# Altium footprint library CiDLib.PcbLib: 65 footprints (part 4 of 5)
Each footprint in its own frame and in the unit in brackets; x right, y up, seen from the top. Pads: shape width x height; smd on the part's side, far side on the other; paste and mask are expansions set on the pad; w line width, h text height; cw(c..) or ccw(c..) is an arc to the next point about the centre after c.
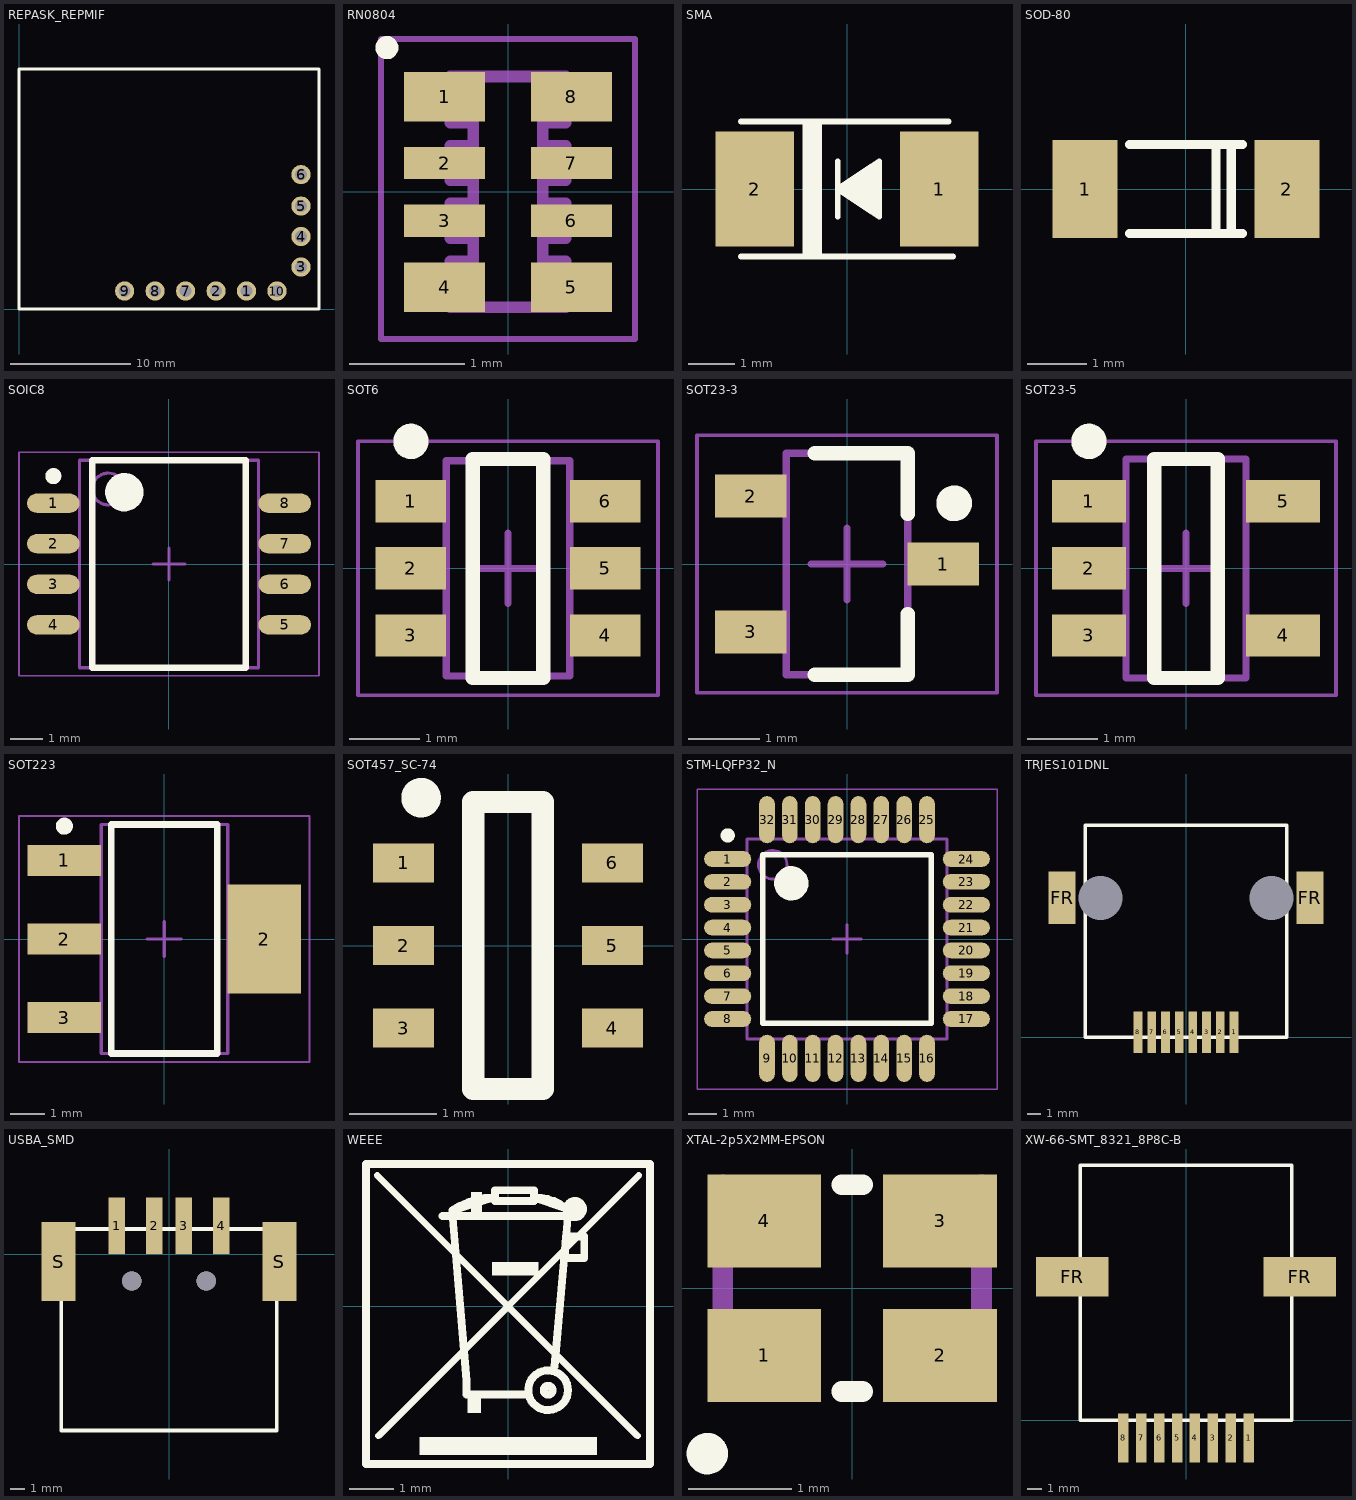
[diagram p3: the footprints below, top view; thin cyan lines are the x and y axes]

## REPASK_REPMIF [mm]
pads (10):
  round 1.6 hole 1: 1(18.96,1.5) 2(16.42,1.5) 3(23.5,3.5) 4(23.5,6.04) 5(23.5,8.58) 6(23.5,11.2) 7(13.88,1.5) 8(11.34,1.5) 9(8.8,1.5) 10(21.5,1.5)
Top Overlay:
  lines w0.254: 0,0 0,20 25,20 25,0 0,0
3D body: height 10, standoff 0, extent 0.001,0.001 24.999,19.999

## RN0804 [mm] "Chip Array, ConvexS, 8-Leads, Pitch 0,50mm,  Body 2,00x1,00mm,  IPC Medium Density"
height 0.6
pads (8):
  rect 0.7x0.43 smd: 1(-0.55,0.825) 4(-0.55,-0.825) 5(0.55,-0.825) 8(0.55,0.825)
  rect 0.7x0.28 smd: 2(-0.55,0.25) 3(-0.55,-0.25) 6(0.55,-0.25) 7(0.55,0.25)
Top Overlay:
  circle w0.1: c-1.05,1.25 r0.05
Top Solder:
  region: 0.2,-0.56 0.2,-1.09 0.8,-1.09 0.8,-0.56
  region: 0.2,1.09 0.2,0.56 0.8,0.56 0.8,1.09
  region: -0.8,-0.56 -0.8,-1.09 -0.2,-1.09 -0.2,-0.56
  region: -0.8,-0.06 -0.8,-0.44 -0.2,-0.44 -0.2,-0.06
  region: 0.2,-0.06 0.2,-0.44 0.8,-0.44 0.8,-0.06
  region: -0.8,1.09 -0.8,0.56 -0.2,0.56 -0.2,1.09
  region: 0.2,0.44 0.2,0.06 0.8,0.06 0.8,0.44
  region: -0.8,0.44 -0.8,0.06 -0.2,0.06 -0.2,0.44
Mechanical 15:
  lines w0.05: -1.1,-1.275 1.1,-1.275 1.1,1.325 -1.1,1.325 -1.1,-1.275
Mechanical 16:
  lines w0.1: -0.5,-1 -0.5,-0.6 -0.3,-0.6 -0.3,-0.4 -0.5,-0.4 -0.5,-0.1 -0.3,-0.1 -0.3,0.1 -0.5,0.1 -0.5,0.4 -0.3,0.4 -0.3,0.6 -0.5,0.6 -0.5,1 0.5,1 0.5,0.6 0.3,0.6 0.3,0.4 0.5,0.4 0.5,0.1 0.3,0.1 0.3,-0.1 0.5,-0.1 0.5,-0.4 0.3,-0.4 0.3,-0.6 0.5,-0.6 0.5,-1 -0.5,-1

## SMA [mm]
pads (2):
  rect 1.7x2.5 smd: 1(2,0) 2(-2,0)
Top Overlay:
  lines w0.127: -2.3,-1.46 2.3,-1.46 ; -2.3,1.46 2.2,1.46 ; -0.9,-1.4 -0.9,1.4 ; -0.8,-1.4 -0.8,1.4 ; -0.7,-1.4 -0.7,1.4 ; -0.6,-1.4 -0.6,1.4 ; -0.2,-0.6 -0.2,0 ; -0.2,0.6 -0.2,0 ; -0.1,0 0,0 ; 0,-0.1 0,0 ; 0,0.1 0,0 ; 0.1,-0.1 0.1,0.1 ; 0.2,-0.2 0.2,0.2 ; 0.3,-0.3 0.3,0.3 ; 0.5,-0.4 0.5,0.4 ; 0.6,-0.5 0.6,0.5 ; -0.2,0 0.4,-0.4 ; -0.2,0 0.4,0.4 ; 0.4,-0.4 0.7,-0.6 0.7,0.6 0.4,0.4 ; 0.4,-0.4 0.4,0.4
3D body "User Library-DO-214AC_SMA.step": height 2.15, standoff -0.05, extent -2.5,-1.35 2.5,1.35

## SOD-80 [mm]
height 1.5
pads (2):
  rect 1.1x1.65 smd mask+0.064: 1(-1.7,0) 2(1.7,0)
Top Overlay:
  lines w0.152: -0.953,-0.75 0.953,-0.75 ; -0.953,0.75 0.953,0.75 ; 0.508,-0.75 0.508,0.75 ; 0.762,-0.75 0.762,0.75

## SOIC8 [mm] "SOIC, 8-Leads, Body 6,20x5,30mm, Pitch 1,27mm, IPC Medium Density"
height 2
pads (8):
  oval 1.65x0.6 smd: 1(-3.625,1.905) 2(-3.625,0.635) 3(-3.625,-0.635) 4(-3.625,-1.905) 5(3.625,-1.905) 6(3.625,-0.635) 7(3.625,0.635) 8(3.625,1.905)
Top Overlay:
  circle w0.25: c-3.625,2.755 r0.125
  circle w0.6: c-1.4,2.25 r0.3
  lines w0.2: -2.4,-3.25 -2.4,3.25 2.4,3.25 2.4,-3.25 -2.4,-3.25
Mechanical 13:
  circle w0.1: c-1.9,2.35 r0.5
  lines w0.1: -2.8,-3.25 -2.8,3.25 2.8,3.25 2.8,-3.25 -2.8,-3.25
Mechanical 15:
  lines w0.05: -4.7,-3.5 -4.7,3.5 4.7,3.5 4.7,-3.5 -4.7,-3.5
  lines w0.1: -0.5,0 0.5,0 ; 0,-0.5 0,0.5
3D body: height 2, standoff 0.1, extent -2.8,-3.25 2.8,3.25

## SOT6 [mm] "SOT23, 6-Leads, Body 2,90x2,80mm, Pitch 0,95mm, IPC Medium Density"
height 1.1
pads (6):
  rect 1x0.6 smd: 1(-1.375,0.95) 2(-1.375,0) 3(-1.375,-0.95) 4(1.375,-0.95) 5(1.375,0) 6(1.375,0.95)
Top Overlay:
  circle w0.25: c-1.375,1.8 r0.125
  lines w0.2: -0.5,-1.55 0.5,-1.55 0.5,1.55 -0.5,1.55 -0.5,-1.55
Mechanical 13:
  lines w0.1: -0.875,-1.525 -0.875,1.525 0.875,1.525 0.875,-1.525 -0.875,-1.525
Mechanical 15:
  lines w0.05: -2.125,-1.8 -2.125,1.8 2.125,1.8 2.125,-1.8 -2.125,-1.8
  lines w0.1: -0.5,0 0.5,0 ; 0,-0.5 0,0.5
3D body: height 1.1, standoff 0.1, extent -0.875,-1.525 0.875,1.525

## SOT23-3 [mm]
height 1.2
pads (3):
  rect 1x0.6 smd: 1(1.35,0) 2(-1.35,0.95) 3(-1.35,-0.95)
Top Overlay:
  circle w0.25: c1.5,0.85 r0.125
  lines w0.2: -0.45,-1.55 0.85,-1.55 0.85,-0.7 ; -0.45,1.55 0.85,1.55 0.85,0.7
Mechanical 13:
  lines w0.1: -0.85,-1.55 -0.85,1.55 0.85,1.55 0.85,-1.55 -0.85,-1.55
Mechanical 15:
  lines w0.05: -2.1,-1.8 -2.1,1.8 2.1,1.8 2.1,-1.8 -2.1,-1.8
  lines w0.1: -0.5,0 0.5,0 ; 0,-0.5 0,0.5
3D body "CircuitWorks-SOT-23.step": height 1.1, standoff 0, extent -1.25,-1.5 1.25,1.5

## SOT23-5 [mm]
height 1.2
pads (5):
  rect 1.05x0.6 smd: 1(-1.375,0.95) 2(-1.375,0) 3(-1.375,-0.95) 4(1.375,-0.95) 5(1.375,0.95)
Top Overlay:
  circle w0.25: c-1.375,1.8 r0.125
  lines w0.2: -0.45,-1.55 -0.45,1.55 0.45,1.55 0.45,-1.55 -0.45,-1.55
Mechanical 13:
  lines w0.1: -0.85,-1.55 0.85,-1.55 0.85,1.55 -0.85,1.55 -0.85,-1.55
Mechanical 15:
  lines w0.05: -2.125,-1.8 2.125,-1.8 2.125,1.8 -2.125,1.8 -2.125,-1.8
  lines w0.1: -0.5,0 0.5,0 ; 0,-0.5 0,0.5
3D body: height 1.2, standoff 0.1, extent -0.85,-1.55 0.85,1.55

## SOT223 [mm] "SOT223, 4-Leads, Body 6,50x7,00mm (avg), Pitch 2,30mm, IPC Medium Density"
height 1.7
pads (4):
  rect 2.15x0.9 smd: 1(-2.925,2.3) 2(-2.925,0) 3(-2.925,-2.3)
  rect 2.15x3.2 smd: 2(2.925,0)
Top Overlay:
  circle w0.25: c-2.925,3.3 r0.125
  lines w0.2: -1.55,-3.35 1.55,-3.35 1.55,3.35 -1.55,3.35 -1.55,-3.35
Mechanical 13:
  lines w0.1: -1.85,-3.35 1.85,-3.35 1.85,3.35 -1.85,3.35 -1.85,-3.35
Mechanical 15:
  lines w0.05: -4.25,-3.6 4.25,-3.6 4.25,3.6 -4.25,3.6 -4.25,-3.6
  lines w0.1: -0.5,0 0.5,0 ; 0,-0.5 0,0.5
3D body "User Library-SOT-223-1.step": height 1.65, standoff 0, extent -3.5,-3.25 3.5,3.25

## SOT457_SC-74 [mm]
pads (6):
  rect 0.7x0.45 smd: 1(-1.2,0.95) 2(-1.2,0) 3(-1.2,-0.95) 4(1.2,-0.95) 5(1.2,0) 6(1.2,0.95)
Top Overlay:
  circle w0.254: c-1,1.7 r0.1
  lines w0.254: -0.4,-1.65 0.4,-1.65 0.4,1.65 -0.4,1.65 -0.4,-1.65
3D body: height 1.1, standoff 0, extent -0.7,-1.7 0.7,1.7

## STM-LQFP32_N [mm] "QFP, 32-Leads, Body 7x7mm, Pitch 0.8mm, IPC Medium Density"
height 1.6
pads (32):
  oval 1.65x0.55 smd: 1(-4.175,2.8) 2(-4.175,2) 3(-4.175,1.2) 4(-4.175,0.4) 5(-4.175,-0.4) 6(-4.175,-1.2) 7(-4.175,-2) 8(-4.175,-2.8) 17(4.175,-2.8) 18(4.175,-2) 19(4.175,-1.2) 20(4.175,-0.4) 21(4.175,0.4) 22(4.175,1.2) 23(4.175,2) 24(4.175,2.8)
  oval 0.55x1.65 smd: 9(-2.8,-4.175) 10(-2,-4.175) 11(-1.2,-4.175) 12(-0.4,-4.175) 13(0.4,-4.175) 14(1.2,-4.175) 15(2,-4.175) 16(2.8,-4.175) 25(2.8,4.175) 26(2,4.175) 27(1.2,4.175) 28(0.4,4.175) 29(-0.4,4.175) 30(-1.2,4.175) 31(-2,4.175) 32(-2.8,4.175)
Top Overlay:
  circle w0.25: c-4.175,3.625 r0.125
  circle w0.6: c-1.95,1.95 r0.3
  lines w0.2: -2.95,-2.95 -2.95,2.95 2.95,2.95 2.95,-2.95 -2.95,-2.95
Mechanical 13:
  circle w0.1: c-2.6,2.6 r0.5
  lines w0.1: -3.5,-3.5 -3.5,3.5 3.5,3.5 3.5,-3.5 -3.5,-3.5
Mechanical 15:
  lines w0.05: -5.25,-5.25 -5.25,5.25 5.25,5.25 5.25,-5.25 -5.25,-5.25
  lines w0.1: -0.5,0 0.5,0 ; 0,-0.5 0,0.5
3D body: height 1.6, standoff 0.05, extent -3.5,-3.5 3.5,3.5

## TRJES101DNL [mm]
pads (12):
  rect 0.65x3.05 smd: 1(3.57,0.37) 2(2.55,0.37) 3(1.53,0.37) 4(0.51,0.37) 5(-0.51,0.37) 6(-1.53,0.37) 7(-2.55,0.37) 8(-3.57,0.37)
  rect 2x3.89 smd: FR(-9.2,10.35) FR(9.2,10.35)
  round 0 hole 3.25 unplated: H(-6.35,10.35) H(6.35,10.35)
Top Overlay:
  lines w0.254: -7.5,0 -7.5,15.75 7.5,15.75 7.5,0 -7.5,0
3D body: height 11.5, standoff 0, extent -7.499,0 7.499,15.749

## USBA_SMD [mm] "USB SMT (1).pdf from Jinglai"
pads (6):
  rect 1.1x3.8 smd: 1(-3.5,1.9) 2(-1,1.9) 3(1,1.9) 4(3.5,1.9)
  rect 2.3x5.3 smd: S(-7.4,-0.5) S(7.4,-0.5)
via -2.5,-1.8 diameter 1.3 hole 1.3
via 2.5,-1.8 diameter 1.3 hole 1.3
Top Overlay:
  lines w0.254: -7.225,-11.825 -7.225,1.675 7.225,1.675 7.225,-11.825 -7.225,-11.825
3D body: height 6.95, standoff 0, extent -7.224,-11.824 7.224,1.674

## WEEE [mm] "WAST ELECTRICAL AND ELECTRONIC EQUIPMENT DIRECTIVE"
height 12.75
Top Overlay:
  circle w0.3: c1.506,2.184 r0.12
  circle w0.178: c0.904,-1.895 r0.099
  circle w0.178: c0.904,-1.895 r0.447
  rectangle: -0.838,1.981 -0.584,2.565
  rectangle: -0.914,-2.413 -0.61,-2.032
  rectangle: -1.993,-3.353 2.007,-2.953
  rectangle: -0.356,0.686 0.686,0.991
  lines w0.152: -2.946,2.946 2.921,-2.921 ; -2.921,-2.921 2.946,2.946
  lines w0.178: -1.473,2.032 1.6,2.032 ; -1.255,2.121 -0.933,-1.676 -0.933,-1.991 0.418,-1.991 ; 1.048,-1.361 1.346,1.989 1.346,1.976 ; 1.29,2.205 0.599,2.438 cw(c0.657,1.473) 1.29,2.205 ; -3.2,-3.556 -3.2,3.2 3.2,3.2 3.2,-3.556 -3.2,-3.556 ; -1.256,2.149 cw(c-0.273,0.706) -0.318,2.451 -1.255,2.149 ; -0.295,2.365 -0.295,2.609 0.584,2.609 0.584,2.365 -0.295,2.365 ; 1.272,1.087 1.302,1.57 1.716,1.57 1.716,1.087 1.272,1.087

## XTAL-2p5X2MM-EPSON [mm]
pads (4):
  rect 1.1x0.9 smd: 1(-0.85,-0.65) 2(0.85,-0.65) 3(0.85,0.65) 4(-0.85,0.65)
Top Overlay:
  circle w0.2: c-1.4,-1.6 r0.1
  lines w0.2: -0.1,-1 0.1,-1 ; -0.1,1 0.1,1
Mechanical 16:
  lines w0.2: -1.25,-1 -1.25,1 ; 1.25,-1 1.25,1
3D body: height 0.8, standoff 0, extent -1.25,-1 1.247,1

## XW-66-SMT_8321_8P8C-B [mm]
pads (10):
  rect 0.75x3.5 smd: 1(4.445,-1.25) 2(3.175,-1.25) 3(1.905,-1.25) 4(0.635,-1.25) 5(-0.635,-1.25) 6(-1.905,-1.25) 7(-3.175,-1.25) 8(-4.445,-1.25)
  rect 5.15x2.8 smd: FR(-8.075,10.2) FR(8.075,10.2)
Top Overlay:
  lines w0.254: -7.5,0 -7.5,18.1 7.5,18.1 7.5,0 -7.5,0
3D body: height 11.5, standoff 0, extent -7.499,0.001 7.499,18.099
